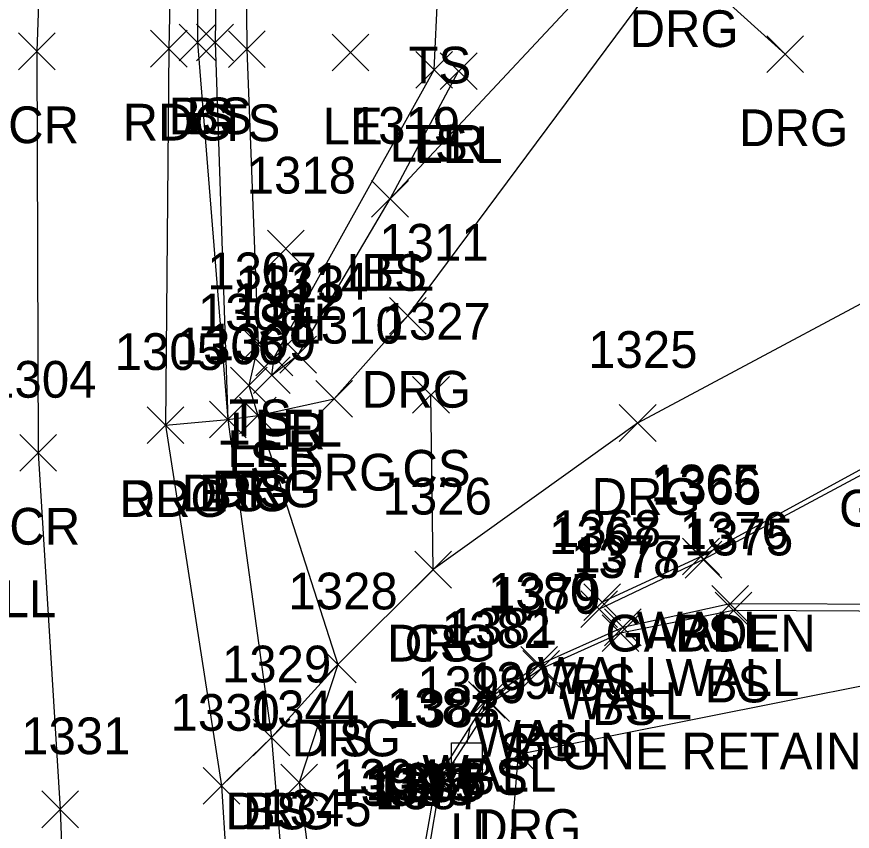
# Model space of a CAD drawing. Extents: x 1657482 to 1661439, y 647981 to 649041.
# Drawn here: x 1659805.99 to 1659851.47, y 648137.91 to 648182.25 of the extents above; entities that cross this region are included whole.
import ezdxf

# ---------------------------------------------------------------- set-up
doc = ezdxf.new("R2010")
doc.units = 0
for name, color, linetype in [('L_A', 7, 'Continuous'), ('L_C', 7, 'Continuous'), ('L_I', 7, 'Continuous'), ('L_TIC', 7, 'Continuous'), ('LAPB', 7, 'Continuous'), ('LARO', 7, 'Continuous'), ('LELB', 7, 'Continuous'), ('LW', 7, 'Continuous'), ('P_A', 7, 'Continuous'), ('P_I', 7, 'Continuous'), ('P_TIC', 7, 'Continuous'), ('PEU', 7, 'Continuous'), ('PRC', 7, 'Continuous'), ('R_A', 7, 'Continuous'), ('R_I', 7, 'Continuous'), ('R_TIC', 7, 'Continuous'), ('RDG', 7, 'Continuous'), ('U_A', 7, 'Continuous'), ('U_I', 7, 'Continuous'), ('ULP', 7, 'Continuous')]:
    doc.layers.add(name, color=color, linetype=linetype)

msp = doc.modelspace()

# ---------------------------------------------------------------- linework, layer by layer
at = {"layer": 'L_TIC'}
for points in [[(1659814.824, 648179.85), (1659816.824, 648181.85)], [(1659816.824, 648179.85), (1659814.824, 648181.85)], [(1659815.785, 648179.856), (1659817.785, 648181.856)], [(1659817.785, 648179.856), (1659815.785, 648181.856)], [(1659817.513, 648179.48), (1659819.513, 648181.48)], [(1659819.513, 648179.48), (1659817.513, 648181.48)], [(1659823.155, 648179.307), (1659825.155, 648181.307)], [(1659825.155, 648179.307), (1659823.155, 648181.307)], [(1659827.715, 648178.361), (1659829.715, 648180.361)], [(1659829.715, 648178.361), (1659827.715, 648180.361)], [(1659827.715, 648178.361), (1659829.715, 648180.361)], [(1659829.715, 648178.361), (1659827.715, 648180.361)], [(1659829.047, 648178.285), (1659831.047, 648180.285)], [(1659831.047, 648178.285), (1659829.047, 648180.285)], [(1659825.31, 648171.334), (1659827.31, 648173.334)], [(1659827.31, 648171.334), (1659825.31, 648173.334)], [(1659825.31, 648171.334), (1659827.31, 648173.334)], [(1659827.31, 648171.334), (1659825.31, 648173.334)], [(1659819.635, 648168.627), (1659821.635, 648170.627)], [(1659821.635, 648168.627), (1659819.635, 648170.627)], [(1659818.139, 648163.418), (1659820.139, 648165.418)], [(1659820.139, 648163.418), (1659818.139, 648165.418)], [(1659819.012, 648162.698), (1659821.012, 648164.698)], [(1659821.012, 648162.698), (1659819.012, 648164.698)], [(1659820.305, 648162.855), (1659822.305, 648164.855)], [(1659822.305, 648162.855), (1659820.305, 648164.855)], [(1659818.878, 648161.745), (1659820.878, 648163.745)], [(1659820.878, 648161.745), (1659818.878, 648163.745)], [(1659818.878, 648161.745), (1659820.878, 648163.745)], [(1659820.878, 648161.745), (1659818.878, 648163.745)], [(1659817.624, 648161.174), (1659819.624, 648163.174)], [(1659819.624, 648161.174), (1659817.624, 648163.174)], [(1659827.54, 648160.67), (1659829.54, 648162.67)], [(1659829.54, 648160.67), (1659827.54, 648162.67)], [(1659816.477, 648159.333), (1659818.477, 648161.333)], [(1659818.477, 648159.333), (1659816.477, 648161.333)], [(1659816.477, 648159.333), (1659818.477, 648161.333)], [(1659818.477, 648159.333), (1659816.477, 648161.333)], [(1659818.118, 648159.547), (1659820.118, 648161.547)], [(1659820.118, 648159.547), (1659818.118, 648161.547)], [(1659842.24, 648151.868), (1659844.24, 648153.868)], [(1659844.24, 648151.868), (1659842.24, 648153.868)], [(1659842.372, 648151.699), (1659844.372, 648153.699)], [(1659844.372, 648151.699), (1659842.372, 648153.699)], [(1659842.372, 648151.699), (1659844.372, 648153.699)], [(1659844.372, 648151.699), (1659842.372, 648153.699)], [(1659827.653, 648151.155), (1659829.653, 648153.155)], [(1659829.653, 648151.155), (1659827.653, 648153.155)], [(1659836.864, 648149.391), (1659838.864, 648151.391)], [(1659838.864, 648149.391), (1659836.864, 648151.391)], [(1659843.82, 648149.286), (1659845.82, 648151.286)], [(1659845.82, 648149.286), (1659843.82, 648151.286)], [(1659836.702, 648149.005), (1659838.702, 648151.005)], [(1659838.702, 648149.005), (1659836.702, 648151.005)], [(1659844.004, 648148.928), (1659846.004, 648150.928)], [(1659846.004, 648148.928), (1659844.004, 648150.928)], [(1659837.98, 648148.014), (1659839.98, 648150.014)], [(1659839.98, 648148.014), (1659837.98, 648150.014)], [(1659837.854, 648147.7), (1659839.854, 648149.7)], [(1659839.854, 648147.7), (1659837.854, 648149.7)], [(1659822.473, 648145.991), (1659824.473, 648147.991)], [(1659824.473, 648145.991), (1659822.473, 648147.991)], [(1659833.425, 648145.977), (1659835.425, 648147.977)], [(1659835.425, 648145.977), (1659833.425, 648147.977)], [(1659833.535, 648145.755), (1659835.535, 648147.755)], [(1659835.535, 648145.755), (1659833.535, 648147.755)], [(1659830.587, 648144.063), (1659832.587, 648146.063)], [(1659832.587, 648144.063), (1659830.587, 648146.063)], [(1659830.811, 648143.891), (1659832.811, 648145.891)], [(1659832.811, 648143.891), (1659830.811, 648145.891)], [(1659818.862, 648142.017), (1659820.862, 648144.017)], [(1659820.862, 648142.017), (1659818.862, 648144.017)], [(1659820.369, 648139.573), (1659822.369, 648141.573)], [(1659822.369, 648139.573), (1659820.369, 648141.573)], [(1659827.828, 648139.693), (1659829.828, 648141.693)], [(1659829.828, 648139.693), (1659827.828, 648141.693)], [(1659828.049, 648139.582), (1659830.049, 648141.582)], [(1659830.049, 648139.582), (1659828.049, 648141.582)]]:
    msp.add_lwpolyline(points, dxfattribs=at)
at = {"layer": 'LAPB'}
msp.add_lwpolyline([(1659867.105, 648165.861), (1659856.082, 648159.505), (1659843.372, 648152.699)], dxfattribs=at)
at = {"layer": 'LARO'}
for points in [[(1659819.878, 648162.745), (1659820.012, 648163.698), (1659828.715, 648179.361)], [(1659819.878, 648162.745), (1659821.305, 648163.855), (1659826.31, 648172.334), (1659830.047, 648179.285)]]:
    msp.add_lwpolyline(points, dxfattribs=at)
at = {"layer": 'LELB'}
for points in [[(1659815.839, 648205.649), (1659815.824, 648180.85), (1659817.477, 648160.333), (1659819.862, 648143.017), (1659820.895, 648130.299), (1659824.063, 648128.86), (1659827.949, 648129.135)], [(1659817.135, 648205.667), (1659816.785, 648180.856), (1659817.477, 648160.333)], [(1659818.296, 648205.712), (1659818.513, 648180.48), (1659819.139, 648164.418), (1659818.624, 648162.174), (1659819.118, 648160.547), (1659823.473, 648146.991), (1659821.369, 648140.573), (1659822.05, 648135.189), (1659825.728, 648132.378)], [(1659828.715, 648179.361), (1659828.906, 648183.62), (1659838.047, 648195.363)], [(1659826.31, 648172.334), (1659840.35, 648187.353)], [(1659828.653, 648152.155), (1659828.54, 648161.67)], [(1659871.273, 648157.801), (1659860.32, 648151.279), (1659855.242, 648149.881), (1659845.004, 648149.928), (1659838.854, 648148.7), (1659834.535, 648146.755), (1659831.811, 648144.891), (1659829.049, 648140.582), (1659828.365, 648136.633), (1659828.338, 648130.373), (1659826.861, 648130.318)], [(1659843.372, 648152.699), (1659837.702, 648150.005)]]:
    msp.add_lwpolyline(points, dxfattribs=at)
at = {"layer": 'LW'}
for points in [[(1659863.73, 648171.502), (1659866.87, 648166.01), (1659856.061, 648159.847), (1659843.24, 648152.868), (1659837.864, 648150.391)], [(1659867.105, 648165.861), (1659871.962, 648158.488), (1659860.111, 648151.601), (1659855.398, 648150.261), (1659844.82, 648150.286), (1659838.98, 648149.014), (1659834.425, 648146.977), (1659831.587, 648145.063), (1659828.828, 648140.693), (1659828.07, 648136.505), (1659828.185, 648136.115), (1659828.219, 648130.534), (1659826.247, 648130.531), (1659825.914, 648136.293), (1659825.834, 648136.838)]]:
    msp.add_lwpolyline(points, dxfattribs=at)
at = {"layer": 'P_TIC'}
for points in [[(1659806.089, 648179.369), (1659808.089, 648181.369)], [(1659808.089, 648179.369), (1659806.089, 648181.369)], [(1659813.267, 648179.513), (1659815.267, 648181.513)], [(1659815.267, 648179.513), (1659813.267, 648181.513)], [(1659813.091, 648159.024), (1659815.091, 648161.024)], [(1659815.091, 648159.024), (1659813.091, 648161.024)], [(1659806.153, 648157.514), (1659808.153, 648159.514)], [(1659808.153, 648157.514), (1659806.153, 648159.514)], [(1659816.14, 648139.384), (1659818.14, 648141.384)], [(1659818.14, 648139.384), (1659816.14, 648141.384)], [(1659807.358, 648138.109), (1659809.358, 648140.109)], [(1659809.358, 648138.109), (1659807.358, 648140.109)]]:
    msp.add_lwpolyline(points, dxfattribs=at)
at = {"layer": 'PEU'}
msp.add_lwpolyline([(1659815.505, 648322.818), (1659814.949, 648287.397), (1659814.827, 648255.089), (1659814.923, 648227.856), (1659814.784, 648205.417), (1659814.267, 648180.513), (1659814.091, 648160.024), (1659817.14, 648140.384), (1659817.844, 648129.177), (1659822.063, 648119.729)], dxfattribs=at)
at = {"layer": 'PRC'}
msp.add_lwpolyline([(1659807.215, 648322.663), (1659808.086, 648286.107), (1659808.383, 648256.053), (1659808.075, 648228.261), (1659807.949, 648205.151), (1659807.089, 648180.369), (1659807.153, 648158.514), (1659808.358, 648139.109), (1659809.074, 648120.362)], dxfattribs=at)
at = {"layer": 'R_TIC'}
for points in [[(1659846.819, 648179.209), (1659848.819, 648181.209)], [(1659848.819, 648179.209), (1659846.819, 648181.209)], [(1659826.285, 648164.972), (1659828.285, 648166.972)], [(1659828.285, 648164.972), (1659826.285, 648166.972)], [(1659822.273, 648160.459), (1659824.273, 648162.459)], [(1659824.273, 648160.459), (1659822.273, 648162.459)], [(1659816.477, 648159.333), (1659818.477, 648161.333)], [(1659818.477, 648159.333), (1659816.477, 648161.333)], [(1659818.118, 648159.547), (1659820.118, 648161.547)], [(1659820.118, 648159.547), (1659818.118, 648161.547)], [(1659813.091, 648159.024), (1659815.091, 648161.024)], [(1659815.091, 648159.024), (1659813.091, 648161.024)], [(1659838.791, 648159.137), (1659840.791, 648161.137)], [(1659840.791, 648159.137), (1659838.791, 648161.137)], [(1659827.653, 648151.155), (1659829.653, 648153.155)], [(1659829.653, 648151.155), (1659827.653, 648153.155)], [(1659822.473, 648145.991), (1659824.473, 648147.991)], [(1659824.473, 648145.991), (1659822.473, 648147.991)], [(1659818.862, 648142.017), (1659820.862, 648144.017)], [(1659820.862, 648142.017), (1659818.862, 648144.017)], [(1659832.301, 648141.115), (1659834.301, 648143.115)], [(1659834.301, 648141.115), (1659832.301, 648143.115)], [(1659816.14, 648139.384), (1659818.14, 648141.384)], [(1659818.14, 648139.384), (1659816.14, 648141.384)]]:
    msp.add_lwpolyline(points, dxfattribs=at)
at = {"layer": 'RDG'}
for points in [[(1659814.091, 648160.024), (1659817.477, 648160.333), (1659819.118, 648160.547), (1659823.273, 648161.459), (1659827.285, 648165.972), (1659841.86, 648185.601), (1659847.819, 648180.209)], [(1659858.052, 648169.881), (1659839.791, 648160.137), (1659828.653, 648152.155), (1659823.473, 648146.991), (1659819.862, 648143.017), (1659817.14, 648140.384)], [(1659817.844, 648129.177), (1659829.376, 648127.656), (1659832.508, 648132.415), (1659833.301, 648142.115), (1659867.369, 648148.895), (1659867.27, 648149.129), (1659872.122, 648156.64)]]:
    msp.add_lwpolyline(points, dxfattribs=at)
at = {"layer": 'ULP'}
for p, q in [((1659830.663, 648143.557), (1659830.496, 648142.723)), ((1659829.663, 648141.057), (1659829.663, 648142.723)), ((1659829.663, 648142.723), (1659831.329, 648142.723)), ((1659831.329, 648142.723), (1659831.329, 648141.057)), ((1659830.496, 648141.89), (1659830.496, 648141.89)), ((1659831.329, 648141.057), (1659829.663, 648141.057)), ((1659830.246, 648140.223), (1659830.496, 648141.057))]:
    msp.add_line(p, q, dxfattribs=at)

# ---------------------------------------------------------------- texts
at = {"layer": 'L_A'}
for s, p in [('TS', (1659827.315, 648178.62)), ('BS', (1659814.265, 648175.85)), ('BS', (1659815.226, 648175.856)), ('TS', (1659816.923, 648175.48)), ('LE', (1659822.643, 648175.307)), ('LER', (1659826.298, 648174.361)), ('TS', (1659827.125, 648174.361)), ('LEL', (1659827.684, 648174.285)), ('LEL', (1659823.948, 648167.334)), ('BS', (1659824.751, 648167.334)), ('SH', (1659819.124, 648164.627)), ('TS', (1659817.548, 648159.418)), ('LEL', (1659818.943, 648158.855)), ('LER', (1659817.595, 648158.698)), ('LER', (1659817.461, 648157.745)), ('LEL', (1659817.516, 648157.745)), ('TS', (1659817.034, 648157.174)), ('CS', (1659826.981, 648156.67)), ('BS', (1659815.918, 648155.333)), ('BS', (1659815.918, 648155.333)), ('TS', (1659817.528, 648155.547)), ('GARDEN', (1659850.752, 648154.505)), ('GARDEN', (1659838.041, 648147.699)), ('WALL', (1659839.728, 648147.868)), ('BS', (1659841.813, 648147.699)), ('CS', (1659827.094, 648147.155)), ('WALL', (1659834.353, 648145.391)), ('WALL', (1659841.309, 648145.286)), ('BS', (1659836.143, 648145.005)), ('BS', (1659843.445, 648144.928)), ('WALL', (1659835.468, 648144.014)), ('BS', (1659837.295, 648143.7)), ('TS', (1659821.883, 648141.991)), ('WALL', (1659830.913, 648141.977)), ('BS', (1659832.976, 648141.755)), ('WALL', (1659828.075, 648140.063)), ('BS', (1659830.252, 648139.891)), ('BS', (1659818.303, 648138.017))]:
    msp.add_text(s, height=2, dxfattribs=at).set_placement(p)
at = {"layer": 'L_C'}
for s, p in [('2.5 STORY WOOD FRAME TOWN HALL', (1659758.655, 648149.566)), ('STONE RETAINING', (1659832.215, 648141.286))]:
    msp.add_text(s, height=2, dxfattribs=at).set_placement(p)
at = {"layer": 'L_I'}
for s, p in [('1319', (1659824.177, 648175.334)), ('1319', (1659824.177, 648175.334)), ('1318', (1659818.51, 648172.627)), ('1307', (1659816.367, 648167.418)), ('1313', (1659817.886, 648166.698)), ('1314', (1659819.18, 648166.855)), ('1312', (1659817.753, 648165.745)), ('1312', (1659817.753, 648165.745)), ('1308', (1659815.853, 648165.174)), ('1327', (1659825.847, 648164.67)), ('1306', (1659814.651, 648163.333)), ('1306', (1659814.651, 648163.333)), ('1309', (1659816.339, 648163.547)), ('1365', (1659840.5, 648155.868)), ('1366', (1659840.576, 648155.699)), ('1366', (1659840.576, 648155.699)), ('1326', (1659825.905, 648155.155)), ('1368', (1659835.124, 648153.391)), ('1367', (1659834.962, 648153.005)), ('1376', (1659842.073, 648153.286)), ('1375', (1659842.312, 648152.928)), ('1377', (1659836.287, 648152.014)), ('1378', (1659836.162, 648151.7)), ('1328', (1659820.78, 648149.991)), ('1380', (1659831.645, 648149.977)), ('1379', (1659831.834, 648149.755)), ('1382', (1659829.118, 648147.891)), ('1381', (1659829.461, 648148.063)), ('1329', (1659817.161, 648146.017)), ('1344', (1659818.676, 648143.573)), ('1384', (1659826.136, 648143.693)), ('1383', (1659826.356, 648143.582)), ('1394', (1659823.141, 648139.838)), ('1394', (1659823.141, 648139.838)), ('1392', (1659823.221, 648139.293)), ('1392', (1659823.221, 648139.293)), ('1393', (1659824.912, 648139.33)), ('1395', (1659824.954, 648139.605)), ('1385', (1659825.377, 648139.505)), ('1386', (1659825.617, 648139.633)), ('1387', (1659825.492, 648139.115)), ('1345', (1659819.357, 648138.189))]:
    msp.add_text(s, height=2, dxfattribs=at).set_placement(p)
at = {"layer": 'P_A'}
for s, p in [('CR', (1659805.522, 648175.369)), ('RDG', (1659811.755, 648175.513)), ('RDG', (1659811.579, 648155.024)), ('CR', (1659805.586, 648153.514))]:
    msp.add_text(s, height=2, dxfattribs=at).set_placement(p)
at = {"layer": 'P_I'}
for s, p in [('1305', (1659811.319, 648163.024)), ('1304', (1659804.381, 648161.514)), ('1330', (1659814.361, 648143.384)), ('1331', (1659806.232, 648142.109))]:
    msp.add_text(s, height=2, dxfattribs=at).set_placement(p)
at = {"layer": 'R_A'}
for p in [(1659839.348, 648180.601), (1659845.307, 648175.209), (1659824.774, 648160.972), (1659820.762, 648156.459), (1659814.965, 648155.333), (1659816.606, 648155.547), (1659811.579, 648155.024), (1659837.279, 648155.137), (1659826.141, 648147.155), (1659820.961, 648141.991), (1659817.35, 648138.017), (1659830.789, 648137.115)]:
    msp.add_text('DRG', height=2, dxfattribs=at).set_placement(p)
at = {"layer": 'R_I'}
for s, p in [('1311', (1659825.727, 648168.972)), ('1310', (1659821.061, 648164.459)), ('1306', (1659814.651, 648163.333)), ('1309', (1659816.339, 648163.547)), ('1305', (1659811.319, 648163.024)), ('1325', (1659837.099, 648163.137)), ('1326', (1659825.905, 648155.155)), ('1328', (1659820.78, 648149.991)), ('1329', (1659817.161, 648146.017)), ('1397', (1659830.609, 648145.115)), ('1330', (1659814.361, 648143.384))]:
    msp.add_text(s, height=2, dxfattribs=at).set_placement(p)
at = {"layer": 'U_A'}
msp.add_text('LI', height=2, dxfattribs=at).set_placement((1659829.598, 648136.89))
at = {"layer": 'U_I'}
msp.add_text('1399', height=2, dxfattribs=at).set_placement((1659827.795, 648144.89))

doc.saveas('drawing.dxf')
